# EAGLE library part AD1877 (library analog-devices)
Single-Supply 16-Bit Stereo ADC Source: http://www.analog.com/static/imported-files/data_sheets/AD1877.pdf
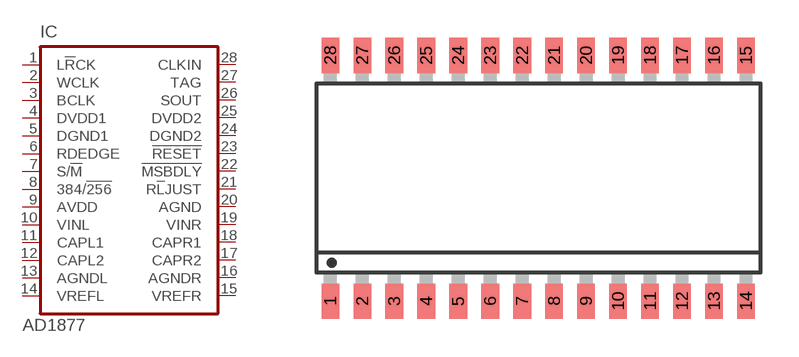
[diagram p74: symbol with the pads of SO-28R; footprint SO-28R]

Designator prefix IC

## AD1877 (MPN: AD1877JRZ; OC_FARNELL: 1438337; OC_NEWARK: 12M8449)  [SO-28R]
1  L!R!CK
2  WCLK
3  BCLK
4  DVDD1  in
5  DGND1  in
6  RDEDGE  in
7  S/!M  in
8  384/!256  in
9  AVDD  in
10  VINL  in
11  CAPL1  out
12  CAPL2  out
13  AGNDL  in
14  VREFL  out
15  VREFR  out
16  AGNDR  in
17  CAPR2  out
18  CAPR1  out
19  VINR  in
20  AGND  in
21  R!L!JUST  in
22  !MSBDLY  in
23  !RESET  in
24  DGND2  in
25  DVDD2  in
26  SOUT  out
27  TAG  out
28  CLKIN  in

## Footprint SO-28R (pad centres in mm)
R-28 (S-Suffix) 28-Lead Wide-Body SO SOL-28 Source: http://www.analog.com/static/imported-files/data_sheets/AD1877.pdf
smd 0.7 x 1.4: 1 -8.255,-4.88; 2 -6.985,-4.88; 3 -5.715,-4.88; 4 -4.445,-4.88; 5 -3.175,-4.88; 6 -1.905,-4.88; 7 -0.635,-4.88; 8 0.635,-4.88; 9 1.905,-4.88; 10 3.175,-4.88; 11 4.445,-4.88; 12 5.715,-4.88; 13 6.985,-4.88; 14 8.255,-4.88; 15 8.255,4.88; 16 6.985,4.88; 17 5.715,4.88; 18 4.445,4.88; 19 3.175,4.88; 20 1.905,4.88; 21 0.635,4.88; 22 -0.635,4.88; 23 -1.905,4.88; 24 -3.175,4.88; 25 -4.445,4.88; 26 -5.715,4.88; 27 -6.985,4.88; 28 -8.255,4.88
